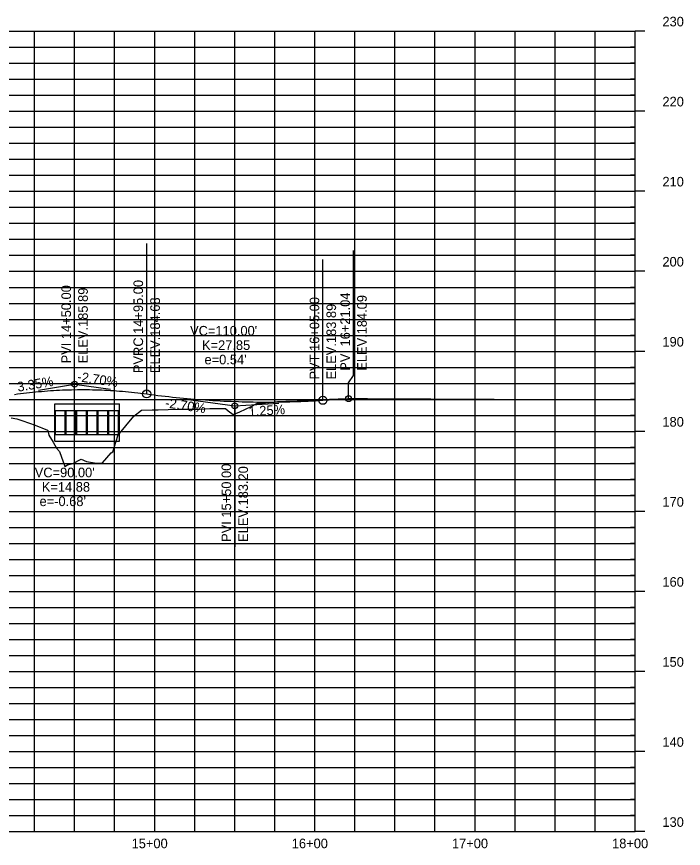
# Model space of a CAD drawing. Extents: x 1409239 to 1412142, y 1838831 to 1842626.
# Drawn here: x 1411258 to 1411674, y 1838831 to 1839350 of the extents above; entities that cross this region are included whole.
import ezdxf

# ---------------------------------------------------------------- set-up
doc = ezdxf.new("R2010")
doc.units = 0
for name, color, linetype in [('R_Axis_Annotation', 7, 'Continuous'), ('R_Drainage', 7, 'Continuous'), ('R_Exist Surface', 7, 'Continuous'), ('R_Grid', 7, 'Continuous'), ('R_Grid Annot', 7, 'Continuous'), ('R_Grid_Minor', 7, 'Continuous'), ('R_Vert Alg', 7, 'Continuous'), ('R_Vert Alg Annot', 7, 'Continuous')]:
    doc.layers.add(name, color=color, linetype=linetype)

msp = doc.modelspace()

# ---------------------------------------------------------------- linework, layer by layer
at = {"layer": 'R_Drainage'}
for p, q in [((1411282.05, 1839085.02), (1411282.05, 1839108.35)), ((1411282.05, 1839108.35), (1411322.38, 1839108.35)), ((1411322.38, 1839085.02), (1411322.38, 1839108.35)), ((1411282.05, 1839104.18), (1411322.38, 1839104.18)), ((1411282.55, 1839089.18), (1411282.55, 1839104.18)), ((1411288.55, 1839089.18), (1411288.55, 1839104.18)), ((1411289.22, 1839089.18), (1411289.22, 1839104.18)), ((1411295.22, 1839089.18), (1411295.22, 1839104.18)), ((1411295.89, 1839089.18), (1411295.89, 1839104.18)), ((1411301.89, 1839089.18), (1411301.89, 1839104.18)), ((1411302.55, 1839089.18), (1411302.55, 1839104.18)), ((1411308.55, 1839089.18), (1411308.55, 1839104.18)), ((1411309.22, 1839089.18), (1411309.22, 1839104.18)), ((1411315.22, 1839089.18), (1411315.22, 1839104.18)), ((1411315.88, 1839089.18), (1411315.88, 1839104.18)), ((1411321.88, 1839089.18), (1411321.88, 1839104.18)), ((1411282.05, 1839089.18), (1411322.38, 1839089.18)), ((1411282.05, 1839085.02), (1411322.38, 1839085.02))]:
    msp.add_line(p, q, dxfattribs=at)
at = {"layer": 'R_Exist Surface'}
msp.add_lwpolyline([(1411254.83, 1839099.6), (1411258.43, 1839098.85), (1411259.6, 1839098.57), (1411262.03, 1839097.73), (1411265.62, 1839096.39), (1411266.85, 1839095.91), (1411269.22, 1839095.09), (1411272.82, 1839093.76), (1411273.99, 1839093.31), (1411277.44, 1839091.88), (1411277.71, 1839091.7), (1411278.42, 1839088.71), (1411281.03, 1839084.31), (1411283.13, 1839080.55), (1411284.94, 1839078.4), (1411288.25, 1839069.06), (1411288.26, 1839069.07), (1411290.02, 1839070.25), (1411293.27, 1839071.09), (1411298.57, 1839073.78), (1411301.92, 1839072.25), (1411308.13, 1839071.12), (1411308.14, 1839071.12), (1411311.92, 1839071.48), (1411317.16, 1839077.63), (1411318.19, 1839078.38), (1411321.4, 1839088.38), (1411321.47, 1839088.45), (1411331.33, 1839100.48), (1411336.26, 1839104.26), (1411342.84, 1839104.59), (1411346.52, 1839104.56), (1411359.07, 1839104.94), (1411367.59, 1839104.86), (1411368.85, 1839104.89), (1411372.44, 1839105), (1411376.03, 1839105.13), (1411378.79, 1839105.25), (1411379.62, 1839105.25), (1411383.2, 1839105.29), (1411386.79, 1839105.35), (1411388.54, 1839105.39), (1411390.38, 1839103.93), (1411393.42, 1839101.56), (1411393.42, 1839101.55), (1411393.96, 1839101.78), (1411397.55, 1839103.37), (1411401.14, 1839105.01), (1411404.73, 1839106.7), (1411408.23, 1839108.41), (1411408.31, 1839108.42), (1411408.37, 1839108.43), (1411408.57, 1839108.44), (1411411.9, 1839108.76), (1411415.49, 1839109.11), (1411419.08, 1839109.48), (1411421.05, 1839109.68), (1411422.66, 1839109.74), (1411426.25, 1839109.88), (1411429.73, 1839110.03), (1411429.84, 1839110.03), (1411433.43, 1839110.16), (1411437.01, 1839110.3), (1411437.4, 1839110.32), (1411440.6, 1839110.49), (1411440.6, 1839110.49), (1411444.28, 1839110.68), (1411447.96, 1839110.86), (1411450.25, 1839110.97), (1411451.63, 1839111.02), (1411453.6, 1839111.09), (1411455.31, 1839111.16), (1411458.99, 1839111.31), (1411462.66, 1839111.44), (1411465.48, 1839111.53), (1411466.34, 1839111.53), (1411470.02, 1839111.51), (1411473.69, 1839111.5), (1411473.87, 1839111.5), (1411477.22, 1839111.5), (1411477.37, 1839111.5), (1411481.05, 1839111.49), (1411484.72, 1839111.47), (1411488.4, 1839111.45), (1411492.08, 1839111.43), (1411493.69, 1839111.43), (1411495.76, 1839111.43), (1411499.43, 1839111.42), (1411502.3, 1839111.42), (1411503.11, 1839111.41), (1411506.79, 1839111.39), (1411510.46, 1839111.36), (1411514.14, 1839111.33), (1411516.85, 1839111.3), (1411527.22, 1839111.26), (1411541.88, 1839111.12), (1411552.12, 1839111.08), (1411556.41, 1839111.11)], dxfattribs=at)
at = {"layer": 'R_Grid'}
for p, q in [((1410844.41, 1839341.03), (1411644.41, 1839341.03)), ((1410844.41, 1839341.03), (1411644.41, 1839341.03)), ((1411344.41, 1838841.03), (1411344.41, 1839341.03)), ((1411444.41, 1838841.03), (1411444.41, 1839341.03)), ((1411544.41, 1838841.03), (1411544.41, 1839341.03)), ((1411644.41, 1838841.03), (1411644.41, 1839341.03)), ((1410844.41, 1839291.03), (1411644.41, 1839291.03)), ((1410844.41, 1839241.03), (1411644.41, 1839241.03)), ((1410844.41, 1839191.03), (1411644.41, 1839191.03)), ((1410844.41, 1839141.03), (1411644.41, 1839141.03)), ((1410844.41, 1839091.03), (1411644.41, 1839091.03)), ((1410844.41, 1839041.03), (1411644.41, 1839041.03)), ((1410844.41, 1838991.03), (1411644.41, 1838991.03)), ((1410844.41, 1838941.03), (1411644.41, 1838941.03)), ((1410844.41, 1838891.03), (1411644.41, 1838891.03)), ((1410844.41, 1838841.03), (1411644.41, 1838841.03))]:
    msp.add_line(p, q, dxfattribs=at)
at = {"layer": 'R_Grid Annot'}
for p, q in [((1411650.41, 1839341.03), (1411644.41, 1839341.03)), ((1411650.41, 1839341.03), (1411644.41, 1839341.03)), ((1411644.41, 1839331.03), (1411641.41, 1839331.03)), ((1411644.41, 1839321.03), (1411641.41, 1839321.03)), ((1411644.41, 1839311.03), (1411641.41, 1839311.03)), ((1411644.41, 1839301.03), (1411641.41, 1839301.03)), ((1411650.41, 1839291.03), (1411644.41, 1839291.03)), ((1411644.41, 1839281.03), (1411641.41, 1839281.03)), ((1411644.41, 1839271.03), (1411641.41, 1839271.03)), ((1411644.41, 1839261.03), (1411641.41, 1839261.03)), ((1411644.41, 1839251.03), (1411641.41, 1839251.03)), ((1411650.41, 1839241.03), (1411644.41, 1839241.03)), ((1411644.41, 1839231.03), (1411641.41, 1839231.03)), ((1411644.41, 1839221.03), (1411641.41, 1839221.03)), ((1411644.41, 1839211.03), (1411641.41, 1839211.03)), ((1411644.41, 1839201.03), (1411641.41, 1839201.03)), ((1411650.41, 1839191.03), (1411644.41, 1839191.03)), ((1411644.41, 1839181.03), (1411641.41, 1839181.03)), ((1411644.41, 1839171.03), (1411641.41, 1839171.03)), ((1411644.41, 1839161.03), (1411641.41, 1839161.03)), ((1411644.41, 1839151.03), (1411641.41, 1839151.03)), ((1411650.41, 1839141.03), (1411644.41, 1839141.03)), ((1411644.41, 1839131.03), (1411641.41, 1839131.03)), ((1411644.41, 1839121.03), (1411641.41, 1839121.03)), ((1411644.41, 1839111.03), (1411641.41, 1839111.03)), ((1411644.41, 1839101.03), (1411641.41, 1839101.03)), ((1411650.41, 1839091.03), (1411644.41, 1839091.03)), ((1411644.41, 1839081.03), (1411641.41, 1839081.03)), ((1411644.41, 1839071.03), (1411641.41, 1839071.03)), ((1411644.41, 1839061.03), (1411641.41, 1839061.03)), ((1411644.41, 1839051.03), (1411641.41, 1839051.03)), ((1411650.41, 1839041.03), (1411644.41, 1839041.03)), ((1411644.41, 1839031.03), (1411641.41, 1839031.03)), ((1411644.41, 1839021.03), (1411641.41, 1839021.03)), ((1411644.41, 1839011.03), (1411641.41, 1839011.03)), ((1411644.41, 1839001.03), (1411641.41, 1839001.03)), ((1411650.41, 1838991.03), (1411644.41, 1838991.03)), ((1411644.41, 1838981.03), (1411641.41, 1838981.03)), ((1411644.41, 1838971.03), (1411641.41, 1838971.03)), ((1411644.41, 1838961.03), (1411641.41, 1838961.03)), ((1411644.41, 1838951.03), (1411641.41, 1838951.03)), ((1411650.41, 1838941.03), (1411644.41, 1838941.03)), ((1411644.41, 1838931.03), (1411641.41, 1838931.03)), ((1411644.41, 1838921.03), (1411641.41, 1838921.03)), ((1411644.41, 1838911.03), (1411641.41, 1838911.03)), ((1411644.41, 1838901.03), (1411641.41, 1838901.03)), ((1411650.41, 1838891.03), (1411644.41, 1838891.03)), ((1411644.41, 1838881.03), (1411641.41, 1838881.03)), ((1411644.41, 1838871.03), (1411641.41, 1838871.03)), ((1411644.41, 1838861.03), (1411641.41, 1838861.03)), ((1411644.41, 1838851.03), (1411641.41, 1838851.03)), ((1411650.41, 1838841.03), (1411644.41, 1838841.03))]:
    msp.add_line(p, q, dxfattribs=at)
at = {"layer": 'R_Grid_Minor'}
for p, q in [((1411269.41, 1838841.03), (1411269.41, 1839341.03)), ((1411294.41, 1838841.03), (1411294.41, 1839341.03)), ((1411319.41, 1838841.03), (1411319.41, 1839341.03)), ((1411369.41, 1838841.03), (1411369.41, 1839341.03)), ((1411394.41, 1838841.03), (1411394.41, 1839341.03)), ((1411419.41, 1838841.03), (1411419.41, 1839341.03)), ((1411469.41, 1838841.03), (1411469.41, 1839341.03)), ((1411494.41, 1838841.03), (1411494.41, 1839341.03)), ((1411519.41, 1838841.03), (1411519.41, 1839341.03)), ((1411569.41, 1838841.03), (1411569.41, 1839341.03)), ((1411594.41, 1838841.03), (1411594.41, 1839341.03)), ((1411619.41, 1838841.03), (1411619.41, 1839341.03)), ((1410844.41, 1839331.03), (1411644.41, 1839331.03)), ((1410844.41, 1839321.03), (1411644.41, 1839321.03)), ((1410844.41, 1839311.03), (1411644.41, 1839311.03)), ((1410844.41, 1839301.03), (1411644.41, 1839301.03)), ((1410844.41, 1839281.03), (1411644.41, 1839281.03)), ((1410844.41, 1839271.03), (1411644.41, 1839271.03)), ((1410844.41, 1839261.03), (1411644.41, 1839261.03)), ((1410844.41, 1839251.03), (1411644.41, 1839251.03)), ((1410844.41, 1839231.03), (1411644.41, 1839231.03)), ((1410844.41, 1839221.03), (1411644.41, 1839221.03)), ((1410844.41, 1839211.03), (1411644.41, 1839211.03)), ((1410844.41, 1839201.03), (1411644.41, 1839201.03)), ((1410844.41, 1839181.03), (1411644.41, 1839181.03)), ((1410844.41, 1839171.03), (1411644.41, 1839171.03)), ((1410844.41, 1839161.03), (1411644.41, 1839161.03)), ((1410844.41, 1839151.03), (1411644.41, 1839151.03)), ((1410844.41, 1839131.03), (1411644.41, 1839131.03)), ((1410844.41, 1839121.03), (1411644.41, 1839121.03)), ((1410844.41, 1839111.03), (1411644.41, 1839111.03)), ((1410844.41, 1839101.03), (1411644.41, 1839101.03)), ((1410844.41, 1839081.03), (1411644.41, 1839081.03)), ((1410844.41, 1839071.03), (1411644.41, 1839071.03)), ((1410844.41, 1839061.03), (1411644.41, 1839061.03)), ((1410844.41, 1839051.03), (1411644.41, 1839051.03)), ((1410844.41, 1839031.03), (1411644.41, 1839031.03)), ((1410844.41, 1839021.03), (1411644.41, 1839021.03)), ((1410844.41, 1839011.03), (1411644.41, 1839011.03)), ((1410844.41, 1839001.03), (1411644.41, 1839001.03)), ((1410844.41, 1838981.03), (1411644.41, 1838981.03)), ((1410844.41, 1838971.03), (1411644.41, 1838971.03)), ((1410844.41, 1838961.03), (1411644.41, 1838961.03)), ((1410844.41, 1838951.03), (1411644.41, 1838951.03)), ((1410844.41, 1838931.03), (1411644.41, 1838931.03)), ((1410844.41, 1838921.03), (1411644.41, 1838921.03)), ((1410844.41, 1838911.03), (1411644.41, 1838911.03)), ((1410844.41, 1838901.03), (1411644.41, 1838901.03)), ((1410844.41, 1838881.03), (1411644.41, 1838881.03)), ((1410844.41, 1838871.03), (1411644.41, 1838871.03)), ((1410844.41, 1838861.03), (1411644.41, 1838861.03)), ((1410844.41, 1838851.03), (1411644.41, 1838851.03))]:
    msp.add_line(p, q, dxfattribs=at)
at = {"layer": 'R_Vert Alg'}
msp.add_line((1411449.41, 1839110.46), (1411465.45, 1839111.47), dxfattribs=at)
for points in [[(1411256.91, 1839114.15), (1411258.79, 1839114.41), (1411260.66, 1839114.66), (1411262.54, 1839114.9), (1411264.41, 1839115.12), (1411266.29, 1839115.34), (1411268.16, 1839115.54), (1411270.04, 1839115.73), (1411271.91, 1839115.91), (1411273.79, 1839116.07), (1411275.66, 1839116.23), (1411277.54, 1839116.37), (1411279.41, 1839116.5), (1411281.29, 1839116.62), (1411283.16, 1839116.73), (1411285.04, 1839116.82), (1411286.91, 1839116.91), (1411288.79, 1839116.98), (1411290.66, 1839117.04), (1411292.54, 1839117.09), (1411296.29, 1839117.15), (1411298.16, 1839117.16), (1411300.04, 1839117.16), (1411301.91, 1839117.15), (1411303.79, 1839117.13), (1411305.66, 1839117.09), (1411307.54, 1839117.05), (1411309.41, 1839116.99), (1411311.29, 1839116.92), (1411313.16, 1839116.84), (1411315.04, 1839116.74), (1411316.91, 1839116.64), (1411318.79, 1839116.52), (1411320.66, 1839116.39), (1411322.54, 1839116.25), (1411324.41, 1839116.1), (1411326.29, 1839115.93), (1411328.16, 1839115.76), (1411330.04, 1839115.57), (1411331.91, 1839115.37), (1411333.79, 1839115.16), (1411335.66, 1839114.93), (1411337.54, 1839114.7), (1411339.41, 1839114.45)], [(1411339.41, 1839114.45), (1411341.71, 1839114.15), (1411344, 1839113.85), (1411346.29, 1839113.57), (1411348.58, 1839113.29), (1411350.87, 1839113.02), (1411353.16, 1839112.77), (1411355.46, 1839112.52), (1411357.75, 1839112.28), (1411360.04, 1839112.05), (1411362.33, 1839111.83), (1411364.62, 1839111.62), (1411366.91, 1839111.42), (1411369.21, 1839111.23), (1411371.5, 1839111.04), (1411373.79, 1839110.87), (1411376.08, 1839110.71), (1411378.37, 1839110.56), (1411380.66, 1839110.41), (1411382.96, 1839110.28), (1411385.25, 1839110.15), (1411387.54, 1839110.03), (1411389.83, 1839109.93), (1411392.12, 1839109.83), (1411396.71, 1839109.66), (1411399, 1839109.6), (1411401.29, 1839109.54), (1411403.58, 1839109.49), (1411405.87, 1839109.45), (1411408.16, 1839109.41), (1411410.46, 1839109.39), (1411412.75, 1839109.38), (1411415.04, 1839109.38), (1411417.33, 1839109.38), (1411419.62, 1839109.4), (1411421.91, 1839109.42), (1411424.21, 1839109.46), (1411426.5, 1839109.5), (1411428.79, 1839109.56), (1411431.08, 1839109.62), (1411433.37, 1839109.69), (1411435.66, 1839109.78), (1411437.96, 1839109.87), (1411440.25, 1839109.97), (1411442.54, 1839110.08), (1411444.83, 1839110.2), (1411447.12, 1839110.33), (1411449.41, 1839110.46)]]:
    msp.add_lwpolyline(points, dxfattribs=at)
at = {"layer": 'R_Vert Alg Annot'}
for p, q in [((1411294.41, 1839130.53), (1411294.41, 1839208.53)), ((1411339.41, 1839124.45), (1411339.41, 1839208.45)), ((1411468.57, 1839125.94), (1411468.57, 1839203.94)), ((1411449.41, 1839120.46), (1411449.41, 1839198.46)), ((1411294.41, 1839120.53), (1411294.41, 1839130.53)), ((1411339.41, 1839114.45), (1411339.41, 1839124.45)), ((1411465.45, 1839121.47), (1411468.57, 1839125.94)), ((1411271.91, 1839116.76), (1411294.41, 1839120.53)), ((1411294.41, 1839120.53), (1411316.91, 1839117.49)), ((1411449.41, 1839110.46), (1411449.41, 1839120.46)), ((1411465.45, 1839111.47), (1411465.45, 1839121.47)), ((1411366.91, 1839110.74), (1411394.41, 1839107.03)), ((1411394.41, 1839107.03), (1411421.91, 1839108.75)), ((1411394.41, 1839107.03), (1411394.41, 1839097.03)), ((1411394.41, 1839097.03), (1411394.41, 1839019.03))]:
    msp.add_line(p, q, dxfattribs=at)
for centre, radius in [((1411294.41, 1839120.53), 1.85), ((1411339.41, 1839114.45), 2.5), ((1411449.41, 1839110.46), 2.5), ((1411465.45, 1839111.47), 1.85), ((1411394.41, 1839107.03), 1.85)]:
    msp.add_circle(centre, radius, dxfattribs=at)

# ---------------------------------------------------------------- texts
at = {"layer": 'R_Axis_Annotation'}
for s, p in [('230', (1411661.42, 1839344.03)), ('230', (1411661.42, 1839344.03)), ('220', (1411661.42, 1839294.03)), ('210', (1411661.42, 1839244.03)), ('200', (1411661.42, 1839194.03)), ('190', (1411661.42, 1839144.03)), ('180', (1411661.42, 1839094.03)), ('170', (1411661.42, 1839044.03)), ('160', (1411661.42, 1838994.03)), ('150', (1411661.42, 1838944.03)), ('140', (1411661.42, 1838894.03)), ('130', (1411661.42, 1838844.03)), ('15+00', (1411330.01, 1838830.68)), ('16+00', (1411430.01, 1838830.68)), ('17+00', (1411530.01, 1838830.68)), ('18+00', (1411630.01, 1838830.68))]:
    msp.add_text(s, height=6, dxfattribs=at).set_placement(p)
at = {"layer": 'R_Vert Alg Annot'}
for s, rotation, p in [('PVRC 14+95.00', 90, (1411337.16, 1839127.45)), ('PVI 14+50.00', 90, (1411292.16, 1839133.53)), ('ELEV.185.89', 90, (1411302.66, 1839133.53)), ('ELEV.184.68', 90, (1411347.66, 1839127.45)), ('PVT 16+05.00', 90, (1411447.16, 1839123.46)), ('PVI 16+21.04', 90, (1411466.32, 1839128.94)), ('ELEV.184.09', 90, (1411476.82, 1839128.94)), ('ELEV.183.89', 90, (1411457.66, 1839123.46)), ('-2.70%', 351.395, (1411295.83, 1839122.47)), ('3.35%', 9.5088, (1411259.1, 1839115.8)), ('-2.70%', 351.395, (1411350.68, 1839106.1)), ('1.25%', 3.5763, (1411403.24, 1839100.45)), ('PVI 15+50.00', 90, (1411392.16, 1839022.03)), ('ELEV.183.20', 90, (1411402.66, 1839022.03))]:
    msp.add_text(s, height=6, rotation=rotation, dxfattribs=at).set_placement(p)
for s, p in [("VC=110.00'", (1411366.51, 1839150.92)), ('K=27.85', (1411373.95, 1839141.92)), ("e=0.54'", (1411375.51, 1839132.92)), ("VC=90.00'", (1411269.51, 1839062.39)), ('K=14.88', (1411273.94, 1839053.39)), ("e=-0.68'", (1411272.52, 1839044.39))]:
    msp.add_text(s, height=6, dxfattribs=at).set_placement(p)

doc.saveas('drawing.dxf')
